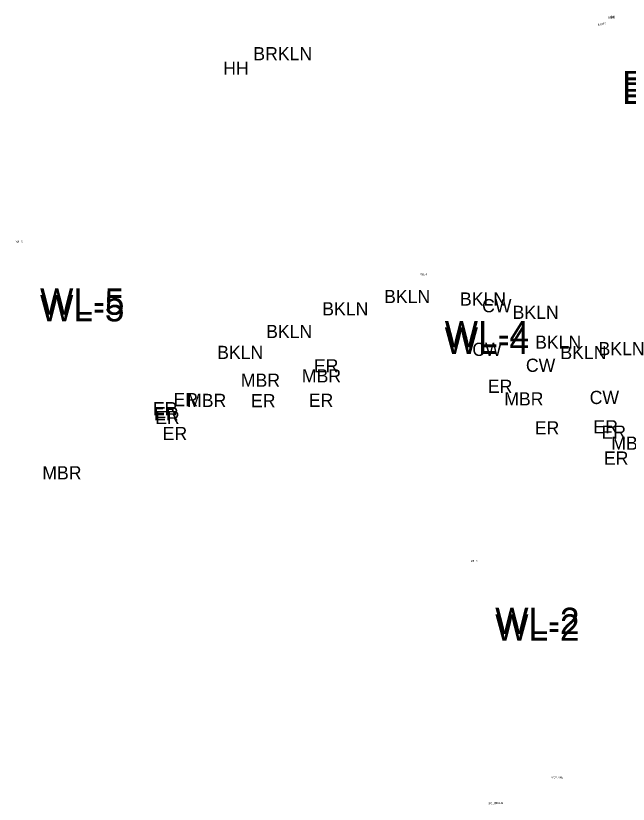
# Model space of a CAD drawing. Extents: x 5447 to 709667, y 4528 to 375472.
# Drawn here: x 706183.1 to 706257.4, y 375095.3 to 375190.8 of the extents above; entities that cross this region are included whole.
import ezdxf

# ---------------------------------------------------------------- set-up
doc = ezdxf.new("R2010")
doc.units = 0
doc.layers.add('SV_SURVEY_NOTES', color=7, linetype='Continuous')

msp = doc.modelspace()

# ---------------------------------------------------------------- texts
at = {"layer": 'SV_SURVEY_NOTES'}
for s, height, p in [('MBR', 0.25, (706255.031, 375190.47)), ('CW', 0.25, (706255.232, 375190.551)), ('ER', 0.25, (706253.74, 375189.654)), ('ER', 0.25, (706254.205, 375189.767)), ('BRKLN', 1.6, (706211.961, 375185.41)), ('HH', 1.6, (706208.306, 375183.652)), ('ER', 3.2, (706256.69, 375180.929)), ('ER', 3.2, (706256.69, 375180.929)), ('ER', 3.2, (706256.69, 375180.929)), ('ER', 3.2, (706256.69, 375180.929)), ('ER', 3.2, (706256.69, 375180.929)), ('ER', 3.2, (706256.69, 375180.929)), ('ER', 3.2, (706256.69, 375180.929)), ('ER', 3.2, (706256.69, 375180.929)), ('ER', 3.2, (706256.69, 375180.129)), ('ER', 3.2, (706256.69, 375180.129)), ('ER', 3.2, (706256.69, 375180.129)), ('WL-5', 0.25, (706183.148, 375163.293)), ('WL-4', 0.25, (706232.223, 375159.354)), ('WL-5', 3.2, (706186.098, 375154.568)), ('WL-5', 3.2, (706186.098, 375154.568)), ('WL-5', 3.2, (706186.098, 375154.568)), ('WL-5', 3.2, (706186.098, 375154.568)), ('WL-5', 3.2, (706186.098, 375154.568)), ('WL-5', 3.2, (706186.098, 375154.568)), ('WL-5', 3.2, (706186.098, 375154.568)), ('WL-5', 3.2, (706186.098, 375154.568)), ('BKLN', 1.6, (706227.821, 375155.985)), ('BKLN', 1.6, (706237.025, 375155.678)), ('WL-5', 3.2, (706186.098, 375153.768)), ('WL-5', 3.2, (706186.098, 375153.768)), ('WL-5', 3.2, (706186.098, 375153.768)), ('CW', 1.6, (706239.708, 375154.868)), ('BKLN', 1.6, (706220.321, 375154.495)), ('BKLN', 1.6, (706243.406, 375154.065)), ('WL-4', 3.2, (706235.173, 375150.629)), ('WL-4', 3.2, (706235.173, 375150.629)), ('WL-4', 3.2, (706235.173, 375150.629)), ('WL-4', 3.2, (706235.173, 375150.629)), ('WL-4', 3.2, (706235.173, 375150.629)), ('WL-4', 3.2, (706235.173, 375150.629)), ('WL-4', 3.2, (706235.173, 375150.629)), ('WL-4', 3.2, (706235.173, 375150.629)), ('BKLN', 1.6, (706213.515, 375151.748)), ('WL-4', 3.2, (706235.173, 375149.829)), ('WL-4', 3.2, (706235.173, 375149.829)), ('WL-4', 3.2, (706235.173, 375149.829)), ('BKLN', 1.6, (706246.133, 375150.449)), ('BKLN', 1.6, (706207.575, 375149.209)), ('CW', 1.6, (706238.514, 375149.585)), ('BKLN', 1.6, (706249.199, 375149.192)), ('BKLN', 1.6, (706253.828, 375149.664)), ('ER', 1.6, (706219.304, 375147.588)), ('CW', 1.6, (706245.018, 375147.649)), ('MBR', 1.6, (706217.851, 375146.367)), ('MBR', 1.6, (706210.448, 375145.838)), ('ER', 1.6, (706240.401, 375145.103)), ('ER', 1.6, (706202.275, 375143.488)), ('MBR', 1.6, (706203.923, 375143.392)), ('ER', 1.6, (706211.678, 375143.361)), ('ER', 1.6, (706218.683, 375143.404)), ('MBR', 1.6, (706242.394, 375143.574)), ('CW', 1.6, (706252.75, 375143.752)), ('ER', 1.6, (706199.782, 375142.384)), ('ER', 1.6, (706199.918, 375141.783)), ('ER', 1.6, (706200.06, 375141.314)), ('ER', 1.6, (706246.09, 375140.064)), ('ER', 1.6, (706253.201, 375140.19)), ('ER', 1.6, (706254.183, 375139.548)), ('ER', 1.6, (706200.966, 375139.382)), ('MBR', 1.6, (706255.371, 375138.212)), ('ER', 1.6, (706254.479, 375136.403)), ('MBR', 1.6, (706186.371, 375134.618)), ('WL-2', 0.25, (706238.345, 375124.595)), ('WL-2', 3.2, (706241.295, 375115.87)), ('WL-2', 3.2, (706241.295, 375115.87)), ('WL-2', 3.2, (706241.295, 375115.87)), ('WL-2', 3.2, (706241.295, 375115.87)), ('WL-2', 3.2, (706241.295, 375115.87)), ('WL-2', 3.2, (706241.295, 375115.87)), ('WL-2', 3.2, (706241.295, 375115.87)), ('WL-2', 3.2, (706241.295, 375115.87)), ('WL-2', 3.2, (706241.295, 375115.07)), ('WL-2', 3.2, (706241.295, 375115.07)), ('WL-2', 3.2, (706241.295, 375115.07)), ('MON WE', 0.25, (706248.064, 375098.396)), ('BCLC', 0.25, (706240.461, 375095.256)), ('BKLN', 0.25, (706241.311, 375095.281))]:
    msp.add_text(s, height=height, dxfattribs=at).set_placement(p)

doc.saveas('drawing.dxf')
